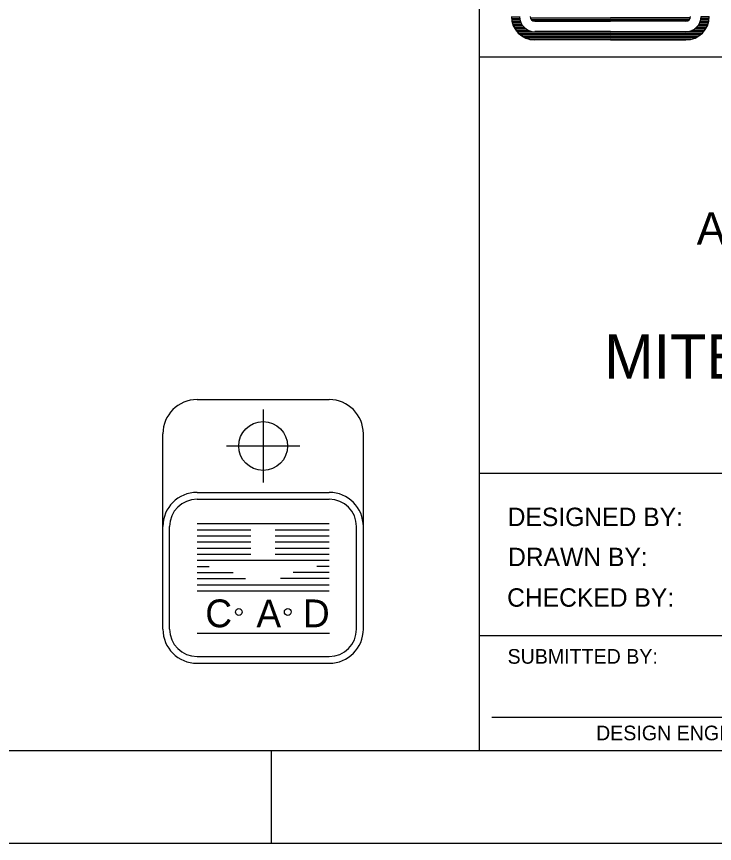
# Model space of a CAD drawing. Extents: x -0.4 to 13.5, y 0 to 9.5.
# Drawn here: x 10.291 to 11.549, y 0.125 to 1.615 of the extents above; entities that cross this region are included whole.
import ezdxf

# ---------------------------------------------------------------- set-up
doc = ezdxf.new("R2010")
doc.units = 0
doc.layers.add('Level 1', color=7, linetype='Continuous')
doc.layers.add('Level 2', color=7, linetype='Continuous')

msp = doc.modelspace()

# ---------------------------------------------------------------- linework, layer by layer
at = {"layer": 'Level 1'}
for p, q in [((11.125, 0.2917), (11.125, 1.875)), ((11.1828, 1.6145), (11.1976, 1.6145)), ((11.1829, 1.6118), (11.1978, 1.6118)), ((11.2169, 1.6126), (11.3611, 1.6126)), ((11.2183, 1.61), (11.3611, 1.61)), ((11.5053, 1.6126), (11.3611, 1.6126)), ((11.5039, 1.61), (11.3611, 1.61)), ((11.5393, 1.6118), (11.5243, 1.6118)), ((11.5394, 1.6145), (11.5245, 1.6145)), ((11.1832, 1.609), (11.1983, 1.609)), ((11.1837, 1.6063), (11.1991, 1.6063)), ((11.1843, 1.6036), (11.2002, 1.6036)), ((11.1852, 1.601), (11.2016, 1.601)), ((11.1863, 1.5983), (11.2035, 1.5983)), ((11.1876, 1.5955), (11.2059, 1.5955)), ((11.222, 1.6073), (11.3611, 1.6073)), ((11.2249, 1.6067), (11.3611, 1.6067)), ((11.5002, 1.6073), (11.3611, 1.6073)), ((11.4973, 1.6067), (11.3611, 1.6067)), ((11.5346, 1.5955), (11.5163, 1.5955)), ((11.5359, 1.5983), (11.5187, 1.5983)), ((11.537, 1.601), (11.5206, 1.601)), ((11.5379, 1.6036), (11.522, 1.6036)), ((11.5385, 1.6063), (11.5231, 1.6063)), ((11.539, 1.609), (11.5238, 1.609)), ((11.1891, 1.5928), (11.2092, 1.5928)), ((11.191, 1.5901), (11.214, 1.5901)), ((11.1931, 1.5875), (11.3611, 1.5875)), ((11.1957, 1.5848), (11.3611, 1.5848)), ((11.1988, 1.582), (11.3611, 1.582)), ((11.3611, 1.5879), (11.2249, 1.5879)), ((11.3611, 1.5879), (11.4973, 1.5879)), ((11.5291, 1.5875), (11.3611, 1.5875)), ((11.5265, 1.5848), (11.3611, 1.5848)), ((11.5234, 1.582), (11.3611, 1.582)), ((11.5312, 1.5901), (11.5082, 1.5901)), ((11.533, 1.5928), (11.513, 1.5928)), ((11.2026, 1.5793), (11.3611, 1.5793)), ((11.2077, 1.5766), (11.3611, 1.5766)), ((11.2159, 1.574), (11.3611, 1.574)), ((11.3611, 1.573), (11.2249, 1.573)), ((11.5195, 1.5793), (11.3611, 1.5793)), ((11.5145, 1.5766), (11.3611, 1.5766)), ((11.5063, 1.574), (11.3611, 1.574)), ((11.3611, 1.573), (11.4973, 1.573)), ((13.2917, 1.5417), (11.125, 1.5417)), ((10.6161, 0.9249), (10.8543, 0.9249)), ((10.7352, 0.9073), (10.7352, 0.7753)), ((10.5545, 0.5112), (10.5545, 0.8633)), ((10.9159, 0.5112), (10.9159, 0.8633)), ((10.6692, 0.8413), (10.8012, 0.8413)), ((13.2917, 0.7917), (11.125, 0.7917)), ((10.6161, 0.7577), (10.8543, 0.7577)), ((10.6161, 0.7454), (10.8543, 0.7454)), ((10.6161, 0.7014), (10.8543, 0.7014)), ((10.5668, 0.5112), (10.5668, 0.6961)), ((10.6161, 0.6904), (10.7132, 0.6904)), ((10.7572, 0.6904), (10.8543, 0.6904)), ((10.9036, 0.5112), (10.9036, 0.6961)), ((10.6161, 0.6794), (10.7132, 0.6794)), ((10.7572, 0.6794), (10.8543, 0.6794)), ((10.6161, 0.6684), (10.7132, 0.6684)), ((10.6161, 0.6573), (10.7132, 0.6573)), ((10.7572, 0.6684), (10.8543, 0.6684)), ((10.7572, 0.6573), (10.8543, 0.6573)), ((10.6161, 0.6463), (10.7132, 0.6463)), ((10.7572, 0.6463), (10.8543, 0.6463)), ((10.6161, 0.6353), (10.8543, 0.6353)), ((10.6161, 0.6243), (10.6381, 0.6243)), ((10.6161, 0.6133), (10.681, 0.6133)), ((10.8542, 0.6133), (10.7894, 0.6133)), ((10.8542, 0.6243), (10.8322, 0.6243)), ((10.6161, 0.6023), (10.7035, 0.6023)), ((10.8542, 0.6023), (10.7668, 0.6023)), ((10.6161, 0.5913), (10.8543, 0.5913)), ((10.6161, 0.5803), (10.8543, 0.5803)), ((10.6161, 0.5039), (10.8547, 0.5039)), ((11.125, 0.5), (11.875, 0.5)), ((10.6161, 0.4619), (10.8543, 0.4619)), ((10.6161, 0.4497), (10.8543, 0.4497)), ((11.1474, 0.3528), (11.8484, 0.3528)), ((10.75, 0.2917), (10.75, 0.125))]:
    msp.add_line(p, q, dxfattribs=at)
for points in [[(0.125, 9.4583), (13.4583, 9.4583), (13.4583, 0.125), (0.125, 0.125)], [(0.625, 9.2917), (13.2917, 9.2917), (13.2917, 0.2917), (0.625, 0.2917)]]:
    msp.add_lwpolyline(points, close=True, dxfattribs=at)
for centre, radius in [((10.7352, 0.8412), 0.044), ((10.6915, 0.5421), 0.00616), ((10.7797, 0.5422), 0.00616)]:
    msp.add_circle(centre, radius, dxfattribs=at)
for centre, radius, start, end in [((11.2249, 1.6151), 0.0422, 180, 270), ((11.2249, 1.6151), 0.0273, 180, 270), ((11.2249, 1.6151), 0.00844, 180, 270), ((11.4972, 1.6151), 0.00844, 270, 0), ((11.4972, 1.6151), 0.0422, 270, 0), ((11.4972, 1.6151), 0.0273, 270, 0), ((10.6161, 0.8632), 0.0616, 90, 180), ((10.8543, 0.8632), 0.0616, 0, 90), ((10.6161, 0.696), 0.0616, 90, 180), ((10.6161, 0.696), 0.0493, 90, 180), ((10.8543, 0.696), 0.0616, 0, 90), ((10.8543, 0.696), 0.0493, 0, 90), ((10.6161, 0.5112), 0.0616, 180, 270), ((10.6161, 0.5112), 0.0493, 180, 270), ((10.8543, 0.5112), 0.0616, 270, 360), ((10.8543, 0.5112), 0.0493, 270, 360)]:
    msp.add_arc(centre, radius, start, end, dxfattribs=at)

# ---------------------------------------------------------------- texts
for s, height, p in [('DESIGNED BY:', 0.033208, (11.176, 0.6969)), ('DRAWN BY:', 0.03321, (11.1767, 0.6247)), ('CHECKED BY:', 0.033208, (11.175, 0.5516)), ('C', 0.0501, (10.631, 0.5146)), ('A', 0.0501, (10.7231, 0.5142)), ('D', 0.0501, (10.8069, 0.5146)), ('SUBMITTED BY:', 0.026417, (11.1758, 0.4489)), ('DESIGN ENGINEER', 0.026417, (11.3353, 0.3109))]:
    msp.add_text(s, height=height, dxfattribs=at).set_placement(p)
at = {"layer": 'Level 2'}
for s, height, p in [('AND HWY. 45 LEVEE CLOSURES', 0.058417, (11.5167, 1.2041)), ('MITER SWING GATE DETAILS', 0.08, (11.35, 0.9623))]:
    msp.add_text(s, height=height, dxfattribs=at).set_placement(p)

doc.saveas('drawing.dxf')
